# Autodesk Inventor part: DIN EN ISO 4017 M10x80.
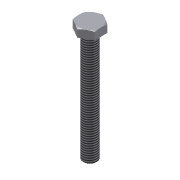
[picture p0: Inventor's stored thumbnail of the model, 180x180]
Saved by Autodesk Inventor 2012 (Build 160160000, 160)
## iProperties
Shininess: 20.0
Length Units: 11269
Angle Units: 11279
Time Units: 11290
Mass Units: 11283
Length Display Precision: 3
Angle Display Precision: 2
Company: CAD-Verlag
Created: 2001-01
Part Number: DIN EN ISO 4017 M10x80.
Material: Steel, Mild
Document SubType Name: Modeling
Description: Sechskantschraube DIN EN ISO 4017 - M10x80.
Standard: DIN EN ISO 4017
Density: 7.86 g/cm^3
Density: 7.859999999999999
Volumn: 5.59798751986722
Area: 24.439342304675858
PropertySet Name: Model Information
Control State: 0
Master: False
Checked Out: False
BOM1: Sechskantschraube
BOM2: M10x80
BOM3: DIN EN ISO 4017
+MSCProtocol1+ProtocolID: P00040924082339696
+MSCProtocol2+Protocol: P00040924082339696<@PID>[Version]<@EL>Version=2.2<@EL>[Data]<@EL>mass=0.060436329{kg<@EL>b=77{mm<@EL>c=0.6{mm<@EL>dw=15{mm<@EL>r=0.4{mm<@EL>s=16{mm<@EL>d=10{mm<
Author: Jürgen Kronas
Revision Number: 1
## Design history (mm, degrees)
node "WorkPlane1"
node "Sketch1"
node "WorkPoint1"
extrude "ExtrusionBlind1" new body distance "d2" = 80 (= prf_l); taper "d3" = 0 deg
  node "Sketch2" dims "d1" = 10 (= prf_d)
chamfer "Chamfer1" distance "d4" = 0.75 (= msp_z); stored, may be unused: second distance "d5" = 0.75 (= msp_z), angle "d31" = 45 deg
node "WorkAxis1"
sketch "Sketch3" dims "d8" = 15 (= prf_dw)
  geometry: C1 r 5 at (0, 0) reference
  constraints: 1 other
extrude "ExtrusionBlind2" join sketch "Sketch3" distance "d9" = 0.6 (= prf_c); taper "d10" = 0 deg
sketch "Sketch4" dims "d13" = 16 (= prf_s)
  geometry: L1 (-8, 4.619)-(-8, -4.619); L2 (0, 9.238)-(-8, 4.619); L3 (8, 4.619)-(0, 9.238); L4 (8, -4.619)-(8, 4.619); L5 (0, -9.238)-(8, -4.619); L6 (-8, -4.619)-(0, -9.238); C1 r 7.5 at (0, 0) reference; C2 r 5 at (0, 0) reference; C3 r 4.25 at (0, 0) reference
  constraints: 12 end point, 4 vertical, 2 parallel, 7 other
extrude "ExtrusionBlind3" join sketch "Sketch4" distance "d14" = 5.8 (= -prf_c + prf_k); taper "d15" = 0 deg
sketch "Sketch5"
  geometry: L1 (-9.238, 5.685)-(-8, 6.4); L2 (0, -50.981)-(0, 0.981); L3 (0, -62.457)-(0, 17.876) reference; L4 (-8, 6.4)-(-9.238, 6.4); L5 (-9.238, 6.4)-(-9.238, 5.685); L6 (-9.238, 0.6)-(-9.238, 6.4) reference
  constraints: 8 end point, 2 perpendicular
  dimensions: "d20" = 0 distance between parallel lines of L6 L5; "d21" = 0 distance from line of L6.end L4; "d22" = 8 distance from line of L3 L1.end (= 0.5 x prf_s); "d23" = 60 deg angle of L6 L1
revolve "RevolutionFull1" sketch "Sketch5" stored, may be unused: angle "d18" = 360 deg
fillet "Fillet1" dims "d19" = 0.4 (= prf_r)
feature "Ms_Thread" dims "d25" = 0, "prf_b" = 77
node "MSC_A1"
node "MSC_PF1"
node "MSC_PT1"
node "Volumenkörper1"
node "Volumenkörpern"
node "Oberflächenkörpern"
other parameters: "prf_p" = 1.5 [user parameter; used in 1 equation term], "prf_l" = 80 [user parameter; used in 1 equation term], "prf_k" = 6.4 [user parameter; used in 1 equation term], "prf_s" = 16 [user parameter; used in 2 equation terms], "prf_r" = 0.4 [user parameter; used in 1 equation term], "prf_dw" = 15 [user parameter; used in 1 equation term], "prf_c" = 0.6 [user parameter; used in 2 equation terms], "msp_z" = 0.75 (= 0.5 x prf_p) [user parameter; used in 2 equation terms], "d6" = 0, "d7" = 15 (derived), "d11" = 0, "d12" = 17 (derived), "d16" = 30 deg (derived), "d28" = 0, "d29" = 0, "d30" = 0
